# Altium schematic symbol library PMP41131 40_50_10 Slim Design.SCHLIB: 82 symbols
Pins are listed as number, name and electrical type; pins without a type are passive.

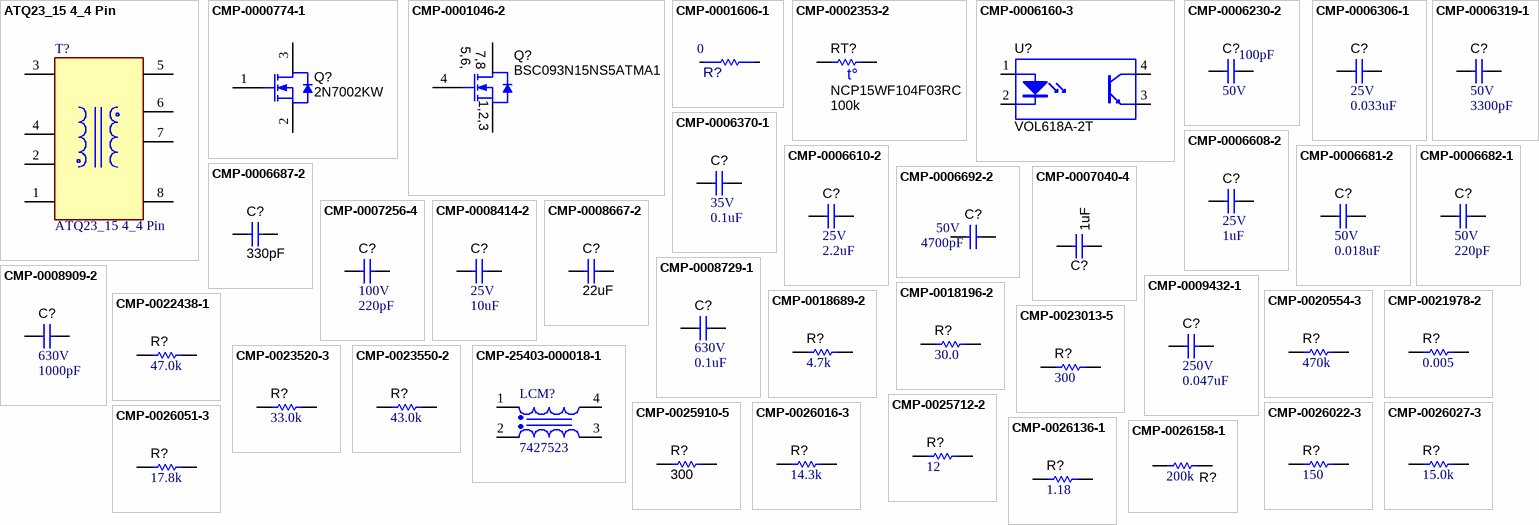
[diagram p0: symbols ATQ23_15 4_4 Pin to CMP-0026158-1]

## ATQ23_15 4_4 Pin
designator T?
footprint ATQ23.7_15 4+4 Pin
pins: 1, 2, 3, 4, 5, 6, 7, 8

## CMP-0000774-1
designator Q?, comment 2N7002KW
MOSFET, N-CH, 60 V, 0.31 A, SOT-323; Alternate Manufacturer: None; Manufacturer: Fairchild Semiconductor; SizeZ_mm: 1.1; ChType: N; Value1: 1; VdsMax_V: 60V; SizeX_mm: 2.2; Vgs_V: 2.1V; Value: 60V; Rdson45_ohm: 1.6; SizeArea_mm2: 4.84; AEC Category: Q101; IdsMax_A: 310mA; SizeAreaWB_mm2: 10.24; U/M: EA
footprint SOT-323 (Diodes Inc recommended land pattern.  2016-02-24)
pins: 1 G, 2 S, 3 D

## CMP-0001046-2
designator Q?, comment BSC093N15NS5ATMA1
MOSFET, N-CH, 150 V, 87 A, PG-TDSON-8; Alternate Manufacturer: None; Manufacturer: Infineon Technologies; SizeZ_mm: 1.12; ChType: N; Value2: 33 nC; VdsMax_V: 150V; SizeX_mm: 5.99; SizeY_mm: 4.9; Vgs_V: 20V; QgTyp_nC: 33; Value: 150V; SizeArea_mm2: 29.351; AEC Category: Q101; IdsMax_A: 87A; SizeAreaWB_mm2: 55.131; U/M: EA
footprint PG-TDSON-8 (Infineon recommended land pattern)
pins: 1 S, 2 S, 3 S, 4 G, 5 D, 6 D, 7 D, 8 D, 9 D

## CMP-0001606-1
designator R?, comment Res_ohm: 0  (hidden comment: CRCW04020000Z0EDHP)
RES Thick Film, 0Ω, 0.2W, 0402; Manufacturer: Vishay Dale; AEC Grade: Grade 0; AEC Qualified: Yes; Power_W: 200mW; SizeZ_mm: 0.4mm; VDC_V: 50V; Value: 0
footprint FP-CRCW04020000Z0EDHP_0402-MFG
footprint FP-CRCW04020000Z0EDHP_0402-IPC_C
footprint FP-CRCW04020000Z0EDHP_0402-IPC_B
footprint FP-CRCW04020000Z0EDHP_0402-IPC_A
pins: 1, 2

## CMP-0002353-2
designator RT?, comment NCP15WF104F03RC  value 100k
Thermistor NTC, 100k ohm, 1%, 0402; Manufacturer: MuRata; TaMax_C: 125°C; SizeX_mm: 1; SizeY_mm: 0.5; TaMin_C: -40°C; Power_W: 100mW; SizeZ_mm: 0.6; SizeAreaWB_mm2: 3; U/M: EA
footprint 0402S (Based on C0402S footprint from PADS legacy)
footprint 0402 (0402 from SM-752 data)
footprint 0402L (0402 from SM-752 data)
footprint 0402M (0402 from SM-752 data)
pins: 1, 2

## CMP-0006160-3
designator U?, comment VOL618A-2T
Optocoupler, 5 kV, 63-125% CTR, SMT; Manufacturer: Vishay-Semiconductor; Manufacturer: Vishay / Semiconductors; CTR (Max): 125%; SizeAreaWB_mm2: 74.42; CTR (Min): 63%; SizeZ_mm: 2.3; SizeX_mm: 10.2; SizeY_mm: 4.1; SizeArea_mm2: 41.82; Voltage_Isolation_Vrms: 5kV
footprint SOP254P1020X230-4 (VISHAY)
pins: 1 A, 2 K, 3 E, 4 C
1 alternate drawing of the same symbol

## CMP-0006230-2
designator C?, comment VDC_V: 50V  ValueDisplayed: 100pF  (hidden comment: 885012205055)
CAP, CERM, 100 pF, 50 V, +/- 10%, X7R, 0402; Manufacturer: Wurth Elektronik; TaMin_C: -55°C; Polarized: N; SizeAreaWB_mm2: 3; Value1: Unknown; U/M: EA; Value: 100pF; TaMax_C: 125°C; SizeZ_mm: 0.6; SizeX_mm: 1; SizeY_mm: 0.5; Cap_Case: 0402; CompType: Capacitor; AEC Category: Q200
footprint 0402 (0402 from SM-752 data)
footprint 0402S (Based on C0402S footprint from PADS legacy)
footprint 0402L (0402 from SM-752 data)
footprint 0402M (0402 from SM-752 data)
pins: 1, 2

## CMP-0006306-1
designator C?, comment VDC_V: 25V  ValueDisplayed: 0.033uF  (hidden comment: CGA2B1X7R1E333K050BC)
CAP, CERM, 0.033 uF, 25 V, +/- 10%, X7R, AEC-Q200 Grade 1, 0402; Manufacturer: TDK; TaMin_C: -55°C; Polarized: N; SizeAreaWB_mm2: 3; Value1: Unknown; U/M: EA; TaMax_C: 125°C; SizeZ_mm: 0.6; SizeX_mm: 1; SizeY_mm: 0.5; Cap_Case: 0402; CompType: Capacitor; AEC Qualified: Y; Cap_F: 33nF; AEC Category: Q200
footprint 0402 (0402 from SM-752 data)
footprint 0402S (Based on C0402S footprint from PADS legacy)
footprint 0402L (0402 from SM-752 data)
footprint 0402M (0402 from SM-752 data)
pins: 1, 2

## CMP-0006319-1
designator C?, comment VDC_V: 50V  ValueDisplayed: 3300pF  (hidden comment: CGA2B2X7R1H332K050BA)
CAP, CERM, 3300 pF, 50 V, +/- 10%, X7R, AEC-Q200 Grade 1, 0402; Manufacturer: TDK; TaMin_C: -55°C; ESR_ohm: 0.7852; Polarized: N; SizeAreaWB_mm2: 3; Value1: 0.785178 ohm; U/M: EA; Value: 3300pF; TaMax_C: 125°C; SizeZ_mm: 0.6; SizeX_mm: 1; SizeY_mm: 0.5; Cap_Case: 0402; CompType: Capacitor; AEC Qualified: Y; Cap_F: 3.3nF; IRMS_A: 272.902mA; AEC Category: Q200
footprint 0402 (0402 from SM-752 data)
footprint 0402S (Based on C0402S footprint from PADS legacy)
footprint 0402L (0402 from SM-752 data)
footprint 0402M (0402 from SM-752 data)
pins: 1, 2

## CMP-0006370-1
designator C?, comment VDC_V: 35V  ValueDisplayed: 0.1uF  (hidden comment: GMK105BJ104KV-F)
CAP, CERM, 0.1 uF, 35 V, +/- 10%, X5R, 0402; Manufacturer: Taiyo Yuden; TaMin_C: -55°C; Polarized: N; SizeAreaWB_mm2: 3; Value1: Unknown; U/M: EA; Value: 0.1uF; TaMax_C: 85°C; SizeZ_mm: 0.6; SizeX_mm: 1; SizeY_mm: 0.5; Cap_Case: 0402; CompType: Capacitor; Cap_F: 100nF; AEC Category: Q200
footprint 0402 (0402 from SM-752 data)
footprint 0402S (Based on C0402S footprint from PADS legacy)
footprint 0402L (0402 from SM-752 data)
footprint 0402M (0402 from SM-752 data)
pins: 1, 2

## CMP-0006608-2
designator C?, comment VDC_V: 25V  ValueDisplayed: 1uF  (hidden comment: GRM155R61E105KA12D)
CAP, CERM, 1 uF, 25 V, +/- 10%, X5R, 0402; Manufacturer: MuRata; TaMin_C: -55°C; Polarized: N; SizeAreaWB_mm2: 3; Value1: Unknown; U/M: EA; Value: 1uF; TaMax_C: 85°C; SizeZ_mm: 0.6; SizeX_mm: 1; SizeY_mm: 0.5; Cap_Case: 0402; CompType: Capacitor; Cap_F: 1µF; AEC Category: Q200
footprint 0402 (0402 from SM-752 data)
footprint 0402S (Based on C0402S footprint from PADS legacy)
footprint 0402L (0402 from SM-752 data)
footprint 0402M (0402 from SM-752 data)
pins: 1, 2

## CMP-0006610-2
designator C?, comment VDC_V: 25V  ValueDisplayed: 2.2uF  (hidden comment: GRM155R61E225KE11D)
CAP, CERM, 2.2 uF, 25 V, +/- 10%, X5R, 0402; Manufacturer: MuRata; TaMin_C: -55°C; Polarized: N; SizeAreaWB_mm2: 3; Value1: Unknown; U/M: EA; Value: 2.2uF; TaMax_C: 85°C; SizeZ_mm: 0.7; SizeX_mm: 1; SizeY_mm: 0.5; Cap_Case: 0402; CompType: Capacitor; Cap_F: 2.2µF; AEC Category: Q200
footprint 0402_070 (SMD, 2-Leads, Body 1.2x0.7mm, Height 0.7mm)
pins: 1, 2

## CMP-0006681-2
designator C?, comment VDC_V: 50V  ValueDisplayed: 0.018uF  (hidden comment: GRM155R71H183KA12D)
CAP, CERM, 0.018 uF, 50 V, +/- 10%, X7R, 0402; Manufacturer: MuRata; TaMin_C: -55°C; Polarized: N; SizeAreaWB_mm2: 3; Value1: Unknown; U/M: EA; TaMax_C: 125°C; SizeZ_mm: 0.6; SizeX_mm: 1; SizeY_mm: 0.5; Cap_Case: 0402; CompType: Capacitor; Cap_F: 18nF; AEC Category: Q200
footprint 0402 (0402 from SM-752 data)
footprint 0402S (Based on C0402S footprint from PADS legacy)
footprint 0402L (0402 from SM-752 data)
footprint 0402M (0402 from SM-752 data)
pins: 1, 2

## CMP-0006682-1
designator C?, comment VDC_V: 50V  ValueDisplayed: 220pF  (hidden comment: GRM155R71H221KA01D)
CAP, CERM, 220 pF, 50 V, +/- 10%, X7R, 0402; Manufacturer: MuRata; TaMin_C: -55°C; Polarized: N; SizeAreaWB_mm2: 3; Value1: Unknown; U/M: EA; Value: 220pF; TaMax_C: 125°C; SizeZ_mm: 0.6; SizeX_mm: 1; SizeY_mm: 0.5; Cap_Case: 0402; CompType: Capacitor; AEC Category: Q200
footprint 0402 (0402 from SM-752 data)
footprint 0402S (Based on C0402S footprint from PADS legacy)
footprint 0402L (0402 from SM-752 data)
footprint 0402M (0402 from SM-752 data)
pins: 1, 2

## CMP-0006687-2
designator C?, comment ValueDisplayed: 330pF  (hidden comment: GRM155R71H331KA01D)
CAP, CERM, 330 pF, 50 V, +/- 10%, X7R, 0402; Manufacturer: MuRata; TaMin_C: -55°C; Polarized: N; SizeAreaWB_mm2: 3; Value1: Unknown; U/M: EA; Value: 330pF; TaMax_C: 125°C; SizeZ_mm: 0.6; SizeX_mm: 1; SizeY_mm: 0.5; Cap_Case: 0402; Value2: 50V; CompType: Capacitor; AEC Category: Q200
footprint 0402 (0402 from SM-752 data)
footprint 0402S (Based on C0402S footprint from PADS legacy)
footprint 0402L (0402 from SM-752 data)
footprint 0402M (0402 from SM-752 data)
pins: 1, 2

## CMP-0006692-2
designator C?, comment VDC_V: 50V  ValueDisplayed: 4700pF  (hidden comment: GRM155R71H472KA01D)
CAP, CERM, 4700 pF, 50 V, +/- 10%, X7R, 0402; Manufacturer: MuRata; TaMin_C: -55°C; Polarized: N; SizeAreaWB_mm2: 3; Value1: Unknown; U/M: EA; Value: 4700pF; TaMax_C: 125°C; SizeZ_mm: 0.6; SizeX_mm: 1; SizeY_mm: 0.5; Cap_Case: 0402; CompType: Capacitor; Cap_F: 4.7nF; AEC Category: Q200
footprint 0402 (0402 from SM-752 data)
footprint 0402S (Based on C0402S footprint from PADS legacy)
footprint 0402L (0402 from SM-752 data)
footprint 0402M (0402 from SM-752 data)
pins: 1, 2

## CMP-0007040-4
designator C?, comment ValueDisplayed: 1uF  (hidden comment: C1608X7R1E105K080AB)
CAP, CERM, 1 µF, 25 V, +/- 10%, X7R, 0603; Manufacturer: TDK; Polarized: N; CompType: Capacitor; Value: 1uF; U/M: EA; Cap_F: 1µF; Value1: Unknown; VDC_V: 25V; TaMin_C: -55°C; TaMax_C: 125°C; Cap_Case: 0603; AEC Category: Q200; SizeArea_mm2: 1.28; SizeAreaWB_mm2: 4.68; SizeX_mm: 1.6; SizeY_mm: 0.8; SizeZ_mm: 1
footprint 0603 (0603 from SM-752 data)
footprint 0603_HV (Ernesto recommended land pattern.  26 mil between pads.)
footprint 0603L (0603 from SM-752 data)
footprint 0603S
footprint 0603M (0603 from SM-752 data)
pins: 1, 2

## CMP-0007256-4
designator C?, comment VDC_V: 100V  ValueDisplayed: 220pF  (hidden comment: GRM1885C2A221JA01D)
CAP, CERM, 220 pF, 100 V, +/- 5%, C0G/NP0, 0603; Manufacturer: MuRata; TaMin_C: -55°C; Polarized: N; SizeAreaWB_mm2: 4.68; Value1: Unknown; U/M: EA; Value: 220pF; TaMax_C: 125°C; SizeZ_mm: 1; SizeX_mm: 1.6; SizeY_mm: 0.8; Cap_Case: 0603; SizeArea_mm2: 1.28; CompType: Capacitor; AEC Category: Q200
footprint 0603 (0603 from SM-752 data)
footprint 0603_HV (Ernesto recommended land pattern.  26 mil between pads.)
footprint 0603L (0603 from SM-752 data)
footprint 0603S
footprint 0603M (0603 from SM-752 data)
pins: 1, 2

## CMP-0008414-2
designator C?, comment VDC_V: 25V  ValueDisplayed: 10uF  (hidden comment: TMK212BBJ106KG-T)
CAP, CERM, 10 uF, 25 V, +/- 10%, X5R, 0805; Manufacturer: Taiyo Yuden; TaMin_C: -55°C; Polarized: N; SizeAreaWB_mm2: 6.75; Value1: Unknown; U/M: EA; Value: 10uF; TaMax_C: 85°C; SizeZ_mm: 1.45; SizeX_mm: 2; SizeY_mm: 1.25; Cap_Case: 0805; SizeArea_mm2: 2.5; CompType: Capacitor; Cap_F: 10µF; AEC Category: Q200
footprint 0805_HV (0805 with 30mil clearance between pads)
footprint 0805M (0805 from SM-752 data)
footprint 0805 (0805 from SM-752 data)
footprint 0805L (0805 from SM-752 data)
footprint 0805_HV1 (Custom footprint based on analyzing multiple manufacturer recommendations)
pins: 1, 2

## CMP-0008667-2
designator C?, comment ValueDisplayed: 22uF  (hidden comment: C3216X5R1V226M160AC)
CAP, CERM, 22 uF, 35 V, +/- 20%, X5R, 1206; Manufacturer: TDK; TaMin_C: -55°C; ESR_ohm: 2.398m; Polarized: N; SizeAreaWB_mm2: 10.92; Value1: 0.002398 ohm; U/M: EA; Value: 22uF; TaMax_C: 85°C; SizeZ_mm: 1.8; SizeX_mm: 3.2; SizeY_mm: 1.6; Cap_Case: 1206_180; Value2: 35V; SizeArea_mm2: 5.12; CompType: Capacitor; Cap_F: 22µF; IRMS_A: 4.68507A; AEC Category: Q200
footprint 1206_180
footprint 1206_180L (1206_180)
footprint 1206_180M (1206_180)
pins: 1, 2

## CMP-0008729-1
designator C?, comment VDC_V: 630V  ValueDisplayed: 0.1uF  (hidden comment: C3216X7T2W104M160AA)
CAP, CERM, 0.1 uF, 450 V, +/- 20%, X7T, 1206; Manufacturer: TDK; TaMin_C: -55°C; Polarized: N; SizeAreaWB_mm2: 10.92; Value1: Unknown; U/M: EA; Value: 0.1uF; TaMax_C: 125°C; SizeZ_mm: 1.8; SizeX_mm: 3.2; SizeY_mm: 1.6; Cap_Case: 1206; Value2: 450V; SizeArea_mm2: 5.12; CompType: Capacitor; Cap_F: 100nF; AEC Category: Q200
footprint 1206_180
footprint 1206_180L (1206_180)
footprint 1206_180M (1206_180)
pins: 1, 2

## CMP-0008909-2
designator C?, comment VDC_V: 630V  ValueDisplayed: 1000pF  (hidden comment: GRM31BR72J102KW01L)
CAP, CERM, 1000 pF, 630 V, +/- 10%, X7R, 1206; Manufacturer: MuRata; TaMin_C: -55°C; Polarized: N; SizeAreaWB_mm2: 10.92; Value1: Unknown; U/M: EA; Value: 1000pF; TaMax_C: 125°C; SizeZ_mm: 1.35; SizeX_mm: 3.2; SizeY_mm: 1.6; Cap_Case: 1206; SizeArea_mm2: 5.12; CompType: Capacitor; Cap_F: 1nF; AEC Category: Q200
footprint 1206 (1206 from SM-752 data)
footprint 1206L (1206 from SM-752 data)
footprint 1206M (1206 from SM-752 data)
pins: 1, 2

## CMP-0009432-1
designator C?, comment VDC_V: 250V  ValueDisplayed: 0.047uF  (hidden comment: GA355ER7GB473KW01L)
CAP, CERM, 0.047 uF, 250 V, +/- 10%, X7R, 2220; Manufacturer: MuRata; TaMin_C: -55°C; Polarized: N; SizeAreaWB_mm2: 53.9; Value1: Unknown; U/M: EA; TaMax_C: 125°C; SizeZ_mm: 2.8; SizeX_mm: 5.7; SizeY_mm: 5; Cap_Case: 2220; SizeArea_mm2: 28.5; CompType: Capacitor; Cap_F: 47nF; AEC Category: Q200
footprint 2220_280 (Chip Capacitor, Body 5.7x5.0mm, IPC Medium Density)
footprint 2220_280L (Chip Capacitor, Body 5.7x5.0mm, IPC High Density)
footprint 2220_280M (Chip Capacitor, Body 5.7x5.0mm, IPC Low Density)
pins: 1, 2

## CMP-0018196-2
designator R?, comment ValueDisplayed: 30.0  (hidden comment: RC1206FR-0730RL)
RES, 30.0, 1%, 0.25 W, 1206; Manufacturer: Yageo America; Power_W: 250mW; TempCo: 100 ppm/C; Value_Code: 30R0; U/M: EA; Value: 30.0; Res_ohm: 30; SizeX_mm: 3.2; SizeY_mm: 1.6; SizeZ_mm: 1.35; Value2: 0.25W; SizeArea_mm2: 5.12; CompType: Resistor; VDC_V: 200V; AEC Category: Q200
footprint 1206 (1206 from SM-752 data)
footprint 1206L (1206 from SM-752 data)
footprint 1206M (1206 from SM-752 data)
pins: 1, 2

## CMP-0018689-2
designator R?, comment ValueDisplayed: 4.7k  (hidden comment: CRCW12064K70JNEA)
RES, 4.7 k, 5%, 0.25 W, 1206; Manufacturer: Vishay-Dale; Manufacturer: Vishay/Dale; Power_W: 250mW; TempCo: 200 ppm/C; Value_Code: 4k70; U/M: EA; Value: 4.7k; EIA_Code: E24; SizeX_mm: 3.2; SizeY_mm: 1.6; SizeZ_mm: 1.35; Value2: 0.25W; SizeArea_mm2: 5.12; CompType: Resistor; VDC_V: 200V; AEC Category: Q200
footprint 1206 (1206 from SM-752 data)
footprint 1206L (1206 from SM-752 data)
footprint 1206M (1206 from SM-752 data)
pins: 1, 2

## CMP-0020554-3
designator R?, comment ValueDisplayed: 470k  (hidden comment: CRCW0805470KJNEA)
RES, 470 k, 5%, 0.125 W, AEC-Q200 Grade 0, 0805; Manufacturer: Vishay-Dale; Manufacturer: Vishay/Dale; Power_W: 125mW; TempCo: 200 ppm/C; Value: 470k; EIA_Code: E24; SizeX_mm: 2; SizeY_mm: 1.25; SizeZ_mm: 1.45; Value2: 0.125W; SizeArea_mm2: 2.5; CompType: Resistor; AEC Qualified: Y; VDC_V: 150V; AEC Category: Q200; AEC Grade: 0
footprint 0805_HV (0805 with 30mil clearance between pads)
footprint 0805M (0805 from SM-752 data)
footprint 0805 (0805 from SM-752 data)
footprint 0805L (0805 from SM-752 data)
footprint 0805_HV1 (Custom footprint based on analyzing multiple manufacturer recommendations)
pins: 1, 2

## CMP-0021978-2
designator R?, comment ValueDisplayed: 0.005  (hidden comment: WSL08055L000FEA)
RES, 0.005, 1%, 0.25 W, 0805; Manufacturer: Vishay-Dale; Manufacturer: Vishay; Power_W: 250mW; TempCo: 110 ppm/C; Value_Code: 5L000; U/M: EA; Value: 0.005; EIA_Code: E96; Res_ohm: 5m; SizeX_mm: 2.03; SizeY_mm: 1.27; SizeZ_mm: 0.584; Value2: 0.25W; SizeArea_mm2: 2.5781; CompType: Resistor; AEC Qualified: N; AEC Category: Q200
footprint WSL0805 (Vishay)
pins: 1, 2

## CMP-0022438-1
designator R?, comment ValueDisplayed: 47.0k  (hidden comment: CRCW060347K0FKEA)
RES, 47.0 k, 1%, 0.1 W, AEC-Q200 Grade 0, 0603; Manufacturer: Vishay-Dale; Manufacturer: Vishay/Dale; Power_W: 100mW; TempCo: 100 ppm/C; Value_Code: 47k0; U/M: EA; Value: 47.0k; Res_ohm: 47k; SizeX_mm: 1.6; SizeY_mm: 0.8; SizeZ_mm: 1; Value2: 0.1W; SizeArea_mm2: 1.28; CompType: Resistor; AEC Qualified: Y; VDC_V: 75V; AEC Grade: 0; AEC Category: Q200
footprint 0603 (0603 from SM-752 data)
footprint 0603_HV (Ernesto recommended land pattern.  26 mil between pads.)
footprint 0603L (0603 from SM-752 data)
footprint 0603S
footprint 0603M (0603 from SM-752 data)
pins: 1, 2

## CMP-0023013-5
designator R?, comment ValueDisplayed: 300  (hidden comment: RC0603FR-07300RL)
RES, 300, 1%, 0.1 W, 0603; Manufacturer: Yageo; Power_W: 100mW; TempCo: 100 ppm/C; Value_Code: 300R; Value: 300; SizeX_mm: 1.6; SizeY_mm: 0.8; SizeZ_mm: 1; Value2: 0.1W; SizeArea_mm2: 1.28; CompType: Resistor; AEC Qualified: N; VDC_V: 75V; AEC Category: Q200; SizeAreaWB_mm2: 4.68
footprint 0603 (0603 from SM-752 data)
footprint 0603_HV (Ernesto recommended land pattern.  26 mil between pads.)
footprint 0603L (0603 from SM-752 data)
footprint 0603S
footprint 0603M (0603 from SM-752 data)
pins: 1, 2

## CMP-0023520-3
designator R?, comment ValueDisplayed: 33.0k  (hidden comment: RG1608P-333-B-T5)
RES, 33.0 k, 0.1%, 0.1 W, 0603; Manufacturer: Susumu Co Ltd; Power_W: 100mW; TempCo: 25 ppm/C; Value_Code: 33k0; U/M: EA; Value: 33.0k; Res_ohm: 33k; SizeX_mm: 1.6; SizeY_mm: 0.8; SizeZ_mm: 1; Value2: 0.1W; SizeArea_mm2: 1.28; CompType: Resistor; VDC_V: 75V; AEC Category: Q200
footprint 0603 (0603 from SM-752 data)
footprint 0603_HV (Ernesto recommended land pattern.  26 mil between pads.)
footprint 0603L (0603 from SM-752 data)
footprint 0603S
footprint 0603M (0603 from SM-752 data)
pins: 1, 2

## CMP-0023550-2
designator R?, comment ValueDisplayed: 43.0k  (hidden comment: RG1608P-433-B-T5)
RES, 43.0 k, 0.1%, 0.1 W, 0603; Manufacturer: Susumu Co Ltd; Power_W: 100mW; TempCo: 25 ppm/C; Value_Code: 43k0; U/M: EA; Value: 43.0k; Res_ohm: 43k; SizeX_mm: 1.6; SizeY_mm: 0.8; SizeZ_mm: 1; Value2: 0.1W; SizeArea_mm2: 1.28; CompType: Resistor; VDC_V: 75V; AEC Category: Q200
footprint 0603 (0603 from SM-752 data)
footprint 0603_HV (Ernesto recommended land pattern.  26 mil between pads.)
footprint 0603L (0603 from SM-752 data)
footprint 0603S
footprint 0603M (0603 from SM-752 data)
pins: 1, 2

## CMP-25403-000018-1
designator LCM?, comment 7427523
WE-CMS SMT Bead Array, size 9085, 83Ohm, 21A; Manufacturer: Wurth Elektronik; Manufacturer: Wurth Electronics; Case/Size Code: 9085; DC Resistance: 3mOhm; Impedance @25MHz: 54Ohm; Rated Voltage: 80V
footprint WE-CMS_9085 (Common Mode SMT Bead, body 9.00x8.50mm)
pins: 1, 2, 3, 4

## CMP-0025712-2
designator R?, comment ValueDisplayed: 12  (hidden comment: CRCW060312R0JNEA)
RES, 12, 5%, 0.1 W, 0603; Manufacturer: Vishay-Dale; Power_W: 100mW; TempCo: 200 ppm/C; Value_Code: 12R0; U/M: EA; Value: 12; EIA_Code: E24; SizeX_mm: 1.6; SizeY_mm: 0.8; SizeZ_mm: 1; Value2: 0.1W; SizeArea_mm2: 1.28; CompType: Resistor; VDC_V: 75V; AEC Category: Q200
footprint 0603 (0603 from SM-752 data)
footprint 0603_HV (Ernesto recommended land pattern.  26 mil between pads.)
footprint 0603L (0603 from SM-752 data)
footprint 0603S
footprint 0603M (0603 from SM-752 data)
pins: 1, 2

## CMP-0025910-5
designator R?, comment ValueDisplayed: 300  (hidden comment: RC0603JR-07300RL)
RES, 300, 5%, 0.1 W, 0603; Manufacturer: Yageo; Power_W: 100mW; TempCo: 100 ppm/C; Value_Code: 300R; Value: 300; EIA_Code: E24; SizeX_mm: 1.6; SizeY_mm: 0.8; SizeZ_mm: 1; Value2: 0.1W; SizeArea_mm2: 1.28; CompType: Resistor; AEC Qualified: N; VDC_V: 75V; AEC Category: Q200; SizeAreaWB_mm2: 4.68
footprint 0603 (0603 from SM-752 data)
footprint 0603_HV (Ernesto recommended land pattern.  26 mil between pads.)
footprint 0603L (0603 from SM-752 data)
footprint 0603S
footprint 0603M (0603 from SM-752 data)
pins: 1, 2

## CMP-0026016-3
designator R?, comment ValueDisplayed: 14.3k  (hidden comment: CRCW040214K3FKED)
RES, 14.3 k, 1%, 0.063 W, AEC-Q200 Grade 0, 0402; Manufacturer: Vishay-Dale; Manufacturer: Vishay / Dale; Power_W: 63mW; TempCo: 100 ppm/C; Value_Code: 14k3; Value: 14.3k; EIA_Code: E96; SizeX_mm: 1; SizeY_mm: 0.5; SizeZ_mm: 0.6; Value2: 0.063W; CompType: Resistor; AEC Qualified: Y; VDC_V: 50V; AEC Category: Q200; AEC Grade: 0
footprint 0402 (0402 from SM-752 data)
footprint 0402S (Based on C0402S footprint from PADS legacy)
footprint 0402L (0402 from SM-752 data)
footprint 0402M (0402 from SM-752 data)
pins: 1, 2

## CMP-0026022-3
designator R?, comment ValueDisplayed: 150  (hidden comment: CRCW0402150RFKED)
RES, 150, 1%, 0.063 W, AEC-Q200 Grade 0, 0402; Manufacturer: Vishay-Dale; Manufacturer: Vishay / Dale; Power_W: 63mW; TempCo: 100 ppm/C; Value_Code: 150R; Value: 150; EIA_Code: E96; SizeX_mm: 1; SizeY_mm: 0.5; SizeZ_mm: 0.6; Value2: 0.063W; CompType: Resistor; AEC Qualified: Y; VDC_V: 50V; AEC Category: Q200; AEC Grade: 0
footprint 0402 (0402 from SM-752 data)
footprint 0402S (Based on C0402S footprint from PADS legacy)
footprint 0402L (0402 from SM-752 data)
footprint 0402M (0402 from SM-752 data)
pins: 1, 2

## CMP-0026027-3
designator R?, comment ValueDisplayed: 15.0k  (hidden comment: CRCW040215K0FKED)
RES, 15.0 k, 1%, 0.063 W, AEC-Q200 Grade 0, 0402; Manufacturer: Vishay-Dale; Manufacturer: Vishay / Dale; Power_W: 63mW; TempCo: 100 ppm/C; Value_Code: 15k0; Value: 15.0k; EIA_Code: E96; Res_ohm: 15k; SizeX_mm: 1; SizeY_mm: 0.5; SizeZ_mm: 0.6; Value2: 0.063W; CompType: Resistor; AEC Qualified: Y; VDC_V: 50V; AEC Category: Q200; AEC Grade: 0
footprint 0402 (0402 from SM-752 data)
footprint 0402S (Based on C0402S footprint from PADS legacy)
footprint 0402L (0402 from SM-752 data)
footprint 0402M (0402 from SM-752 data)
pins: 1, 2

## CMP-0026051-3
designator R?, comment ValueDisplayed: 17.8k  (hidden comment: CRCW040217K8FKED)
RES, 17.8 k, 1%, 0.063 W, AEC-Q200 Grade 0, 0402; Manufacturer: Vishay-Dale; Manufacturer: Vishay / Dale; Power_W: 63mW; TempCo: 100 ppm/C; Value_Code: 17k8; Value: 17.8k; EIA_Code: E96; SizeX_mm: 1; SizeY_mm: 0.5; SizeZ_mm: 0.6; Value2: 0.063W; CompType: Resistor; AEC Qualified: Y; VDC_V: 50V; AEC Category: Q200; AEC Grade: 0
footprint 0402 (0402 from SM-752 data)
footprint 0402S (Based on C0402S footprint from PADS legacy)
footprint 0402L (0402 from SM-752 data)
footprint 0402M (0402 from SM-752 data)
pins: 1, 2

## CMP-0026136-1
designator R?, comment ValueDisplayed: 1.18  (hidden comment: CRCW04021R18FKED)
RES, 1.18, 1%, 0.063 W, 0402; Manufacturer: Vishay-Dale; Power_W: 63mW; TempCo: 100 ppm/C; Value_Code: 1R18; U/M: EA; Value: 1.18; EIA_Code: E96; SizeX_mm: 1; SizeY_mm: 0.5; SizeZ_mm: 0.6; Value2: 0.063W; CompType: Resistor; VDC_V: 50V; AEC Category: Q200
footprint 0402 (0402 from SM-752 data)
footprint 0402S (Based on C0402S footprint from PADS legacy)
footprint 0402L (0402 from SM-752 data)
footprint 0402M (0402 from SM-752 data)
pins: 1, 2

## CMP-0026158-1
designator R?, comment ValueDisplayed: 200k  (hidden comment: CRCW0402200KFKED)
RES, 200 k, 1%, 0.063 W, 0402; Manufacturer: Vishay-Dale; Power_W: 63mW; TempCo: 100 ppm/C; U/M: EA; Value: 200k; EIA_Code: E96; SizeX_mm: 1; SizeY_mm: 0.5; SizeZ_mm: 0.6; Value2: 0.063W; CompType: Resistor; VDC_V: 50V; AEC Category: Q200
footprint 0402 (0402 from SM-752 data)
footprint 0402S (Based on C0402S footprint from PADS legacy)
footprint 0402L (0402 from SM-752 data)
footprint 0402M (0402 from SM-752 data)
pins: 1, 2

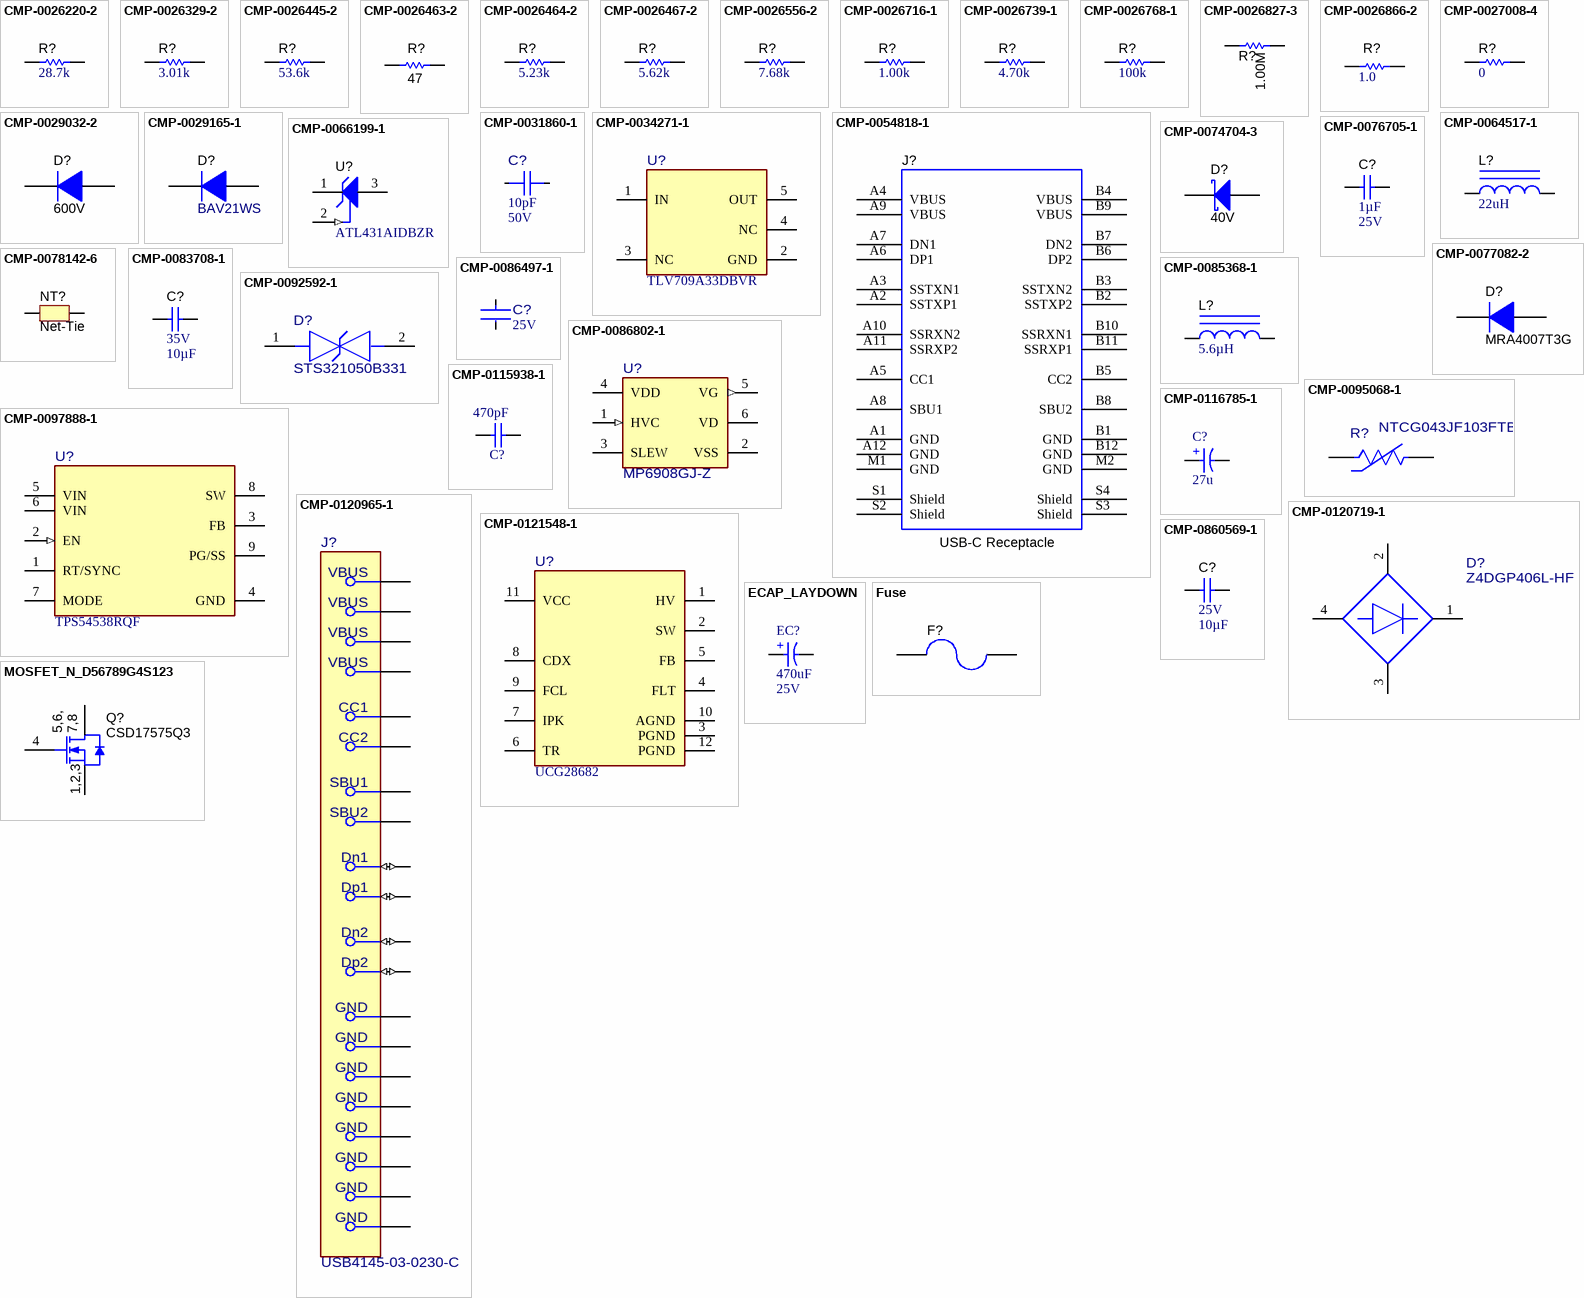
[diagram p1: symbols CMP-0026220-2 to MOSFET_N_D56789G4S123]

## CMP-0026220-2
designator R?, comment ValueDisplayed: 28.7k  (hidden comment: CRCW040228K7FKED)
RES, 28.7 k, 1%, 0.063 W, AEC-Q200 Grade 0, 0402; Manufacturer: Vishay-Dale; Power_W: 63mW; TempCo: 100 ppm/C; Value_Code: 28k7; Value: 28.7k; EIA_Code: E96; SizeX_mm: 1; SizeY_mm: 0.5; SizeZ_mm: 0.6; Value2: 0.063W; CompType: Resistor; AEC Qualified: Y; VDC_V: 50V; AEC Category: Q200; AEC Grade: 0
footprint 0402 (0402 from SM-752 data)
footprint 0402S (Based on C0402S footprint from PADS legacy)
footprint 0402L (0402 from SM-752 data)
footprint 0402M (0402 from SM-752 data)
pins: 1, 2

## CMP-0026329-2
designator R?, comment ValueDisplayed: 3.01k  (hidden comment: CRCW04023K01FKED)
RES, 3.01 k, 1%, 0.063 W, AEC-Q200 Grade 0, 0402; Manufacturer: Vishay-Dale; Power_W: 63mW; TempCo: 100 ppm/C; Value_Code: 3k01; Value: 3.01k; EIA_Code: E96; SizeX_mm: 1; SizeY_mm: 0.5; SizeZ_mm: 0.6; Value2: 0.063W; CompType: Resistor; AEC Qualified: Y; VDC_V: 50V; AEC Category: Q200; AEC Grade: 0
footprint 0402 (0402 from SM-752 data)
footprint 0402S (Based on C0402S footprint from PADS legacy)
footprint 0402L (0402 from SM-752 data)
footprint 0402M (0402 from SM-752 data)
pins: 1, 2

## CMP-0026445-2
designator R?, comment ValueDisplayed: 53.6k  (hidden comment: CRCW040253K6FKED)
RES, 53.6 k, 1%, 0.063 W, AEC-Q200 Grade 0, 0402; Manufacturer: Vishay-Dale; Power_W: 63mW; TempCo: 100 ppm/C; Value_Code: 53k6; Value: 53.6k; EIA_Code: E96; SizeX_mm: 1; SizeY_mm: 0.5; SizeZ_mm: 0.6; Value2: 0.063W; CompType: Resistor; AEC Qualified: Y; VDC_V: 50V; AEC Category: Q200; AEC Grade: 0
footprint 0402 (0402 from SM-752 data)
footprint 0402S (Based on C0402S footprint from PADS legacy)
footprint 0402L (0402 from SM-752 data)
footprint 0402M (0402 from SM-752 data)
pins: 1, 2

## CMP-0026463-2
designator R?, comment ValueDisplayed: 47  (hidden comment: CRCW040247R0JNED)
RES, 47, 5%, 0.063 W, 0402; Manufacturer: Vishay-Dale; Power_W: 63mW; TempCo: 200 ppm/C; Value: 47; EIA_Code: E96; SizeX_mm: 1; SizeY_mm: 0.5; SizeZ_mm: 0.6; Value2: 0.063W; CompType: Resistor; AEC Qualified: Y; VDC_V: 50V; AEC Category: Q200; AEC Grade: 0
footprint 0402 (0402 from SM-752 data)
footprint 0402S (Based on C0402S footprint from PADS legacy)
footprint 0402L (0402 from SM-752 data)
footprint 0402M (0402 from SM-752 data)
pins: 1, 2

## CMP-0026464-2
designator R?, comment ValueDisplayed: 5.23k  (hidden comment: CRCW04025K23FKED)
RES, 5.23 k, 1%, 0.063 W, AEC-Q200 Grade 0, 0402; Manufacturer: Vishay-Dale; Power_W: 63mW; TempCo: 100 ppm/C; Value_Code: 5k23; Value: 5.23k; EIA_Code: E96; SizeX_mm: 1; SizeY_mm: 0.5; SizeZ_mm: 0.6; Value2: 0.063W; CompType: Resistor; AEC Qualified: Y; VDC_V: 50V; AEC Category: Q200; AEC Grade: 0
footprint 0402 (0402 from SM-752 data)
footprint 0402S (Based on C0402S footprint from PADS legacy)
footprint 0402L (0402 from SM-752 data)
footprint 0402M (0402 from SM-752 data)
pins: 1, 2

## CMP-0026467-2
designator R?, comment ValueDisplayed: 5.62k  (hidden comment: CRCW04025K62FKED)
RES, 5.62 k, 1%, 0.063 W, AEC-Q200 Grade 0, 0402; Manufacturer: Vishay-Dale; Power_W: 63mW; TempCo: 100 ppm/C; Value_Code: 5k62; Value: 5.62k; EIA_Code: E96; SizeX_mm: 1; SizeY_mm: 0.5; SizeZ_mm: 0.6; Value2: 0.063W; CompType: Resistor; AEC Qualified: Y; VDC_V: 50V; AEC Category: Q200; AEC Grade: 0
footprint 0402 (0402 from SM-752 data)
footprint 0402S (Based on C0402S footprint from PADS legacy)
footprint 0402L (0402 from SM-752 data)
footprint 0402M (0402 from SM-752 data)
pins: 1, 2

## CMP-0026556-2
designator R?, comment ValueDisplayed: 7.68k  (hidden comment: CRCW04027K68FKED)
RES, 7.68 k, 1%, 0.063 W, AEC-Q200 Grade 0, 0402; Manufacturer: Vishay-Dale; Power_W: 63mW; TempCo: 100 ppm/C; Value_Code: 7k68; Value: 7.68k; EIA_Code: E96; SizeX_mm: 1; SizeY_mm: 0.5; SizeZ_mm: 0.6; Value2: 0.063W; CompType: Resistor; AEC Qualified: Y; VDC_V: 50V; AEC Category: Q200; AEC Grade: 0
footprint 0402 (0402 from SM-752 data)
footprint 0402S (Based on C0402S footprint from PADS legacy)
footprint 0402L (0402 from SM-752 data)
footprint 0402M (0402 from SM-752 data)
pins: 1, 2

## CMP-0026716-1
designator R?, comment ValueDisplayed: 1.00k  (hidden comment: MCR01MZPF1001)
RES, 1.00 k, 1%, 0.063 W, 0402; Manufacturer: Rohm; Power_W: 63mW; TempCo: 100 ppm/C; Value_Code: 1k00; U/M: EA; Value: 1.00k; EIA_Code: E96; Res_ohm: 1k; SizeX_mm: 1; SizeY_mm: 0.5; SizeZ_mm: 0.6; Value2: 0.063W; CompType: Resistor; AEC Qualified: N; VDC_V: 50V; AEC Category: Q200
footprint 0402 (0402 from SM-752 data)
footprint 0402S (Based on C0402S footprint from PADS legacy)
footprint 0402L (0402 from SM-752 data)
footprint 0402M (0402 from SM-752 data)
pins: 1, 2

## CMP-0026739-1
designator R?, comment ValueDisplayed: 4.70k  (hidden comment: RC0402FR-074K7L)
RES, 4.70 k, 1%, 0.0625 W, 0402; Manufacturer: Yageo America; Power_W: 62.5mW; TempCo: 100 ppm/C; Value_Code: 4k70; U/M: EA; Value: 4.70k; Res_ohm: 4.7k; SizeX_mm: 1; SizeY_mm: 0.5; SizeZ_mm: 0.6; CompType: Resistor; AEC Qualified: N; VDC_V: 50V; AEC Category: Q200
footprint 0402 (0402 from SM-752 data)
footprint 0402S (Based on C0402S footprint from PADS legacy)
footprint 0402L (0402 from SM-752 data)
footprint 0402M (0402 from SM-752 data)
pins: 1, 2

## CMP-0026768-1
designator R?, comment ValueDisplayed: 100k  (hidden comment: CRCW0402100KDHEDP)
RES, 100 k, 0.5%, 0.063 W, 0402; Manufacturer: Vishay-Dale; Power_W: 63mW; TempCo: 50 ppm/C; U/M: EA; Value: 100k; EIA_Code: E192; SizeX_mm: 1; SizeY_mm: 0.5; SizeZ_mm: 0.6; Value2: 0.063W; CompType: Resistor; VDC_V: 50V; AEC Category: Q200
footprint 0402 (0402 from SM-752 data)
footprint 0402S (Based on C0402S footprint from PADS legacy)
footprint 0402L (0402 from SM-752 data)
footprint 0402M (0402 from SM-752 data)
pins: 1, 2

## CMP-0026827-3
designator R?, comment ValueDisplayed: 1.00M  (hidden comment: RMCF0402FT1M00)
RES, 1.00 M, 1%, 0.063 W, AEC-Q200 Grade 0, 0402; Manufacturer: Stackpole Electronics Inc; Manufacturer: Vishay / Dale; Manufacturer Part Number: CRCW040210R0JNED; CompType: Resistor; Value: 1.0Meg; Power_W: 63mW; Value2: 0.063W; VDC_V: 50V; TempCo: 200 ppm/C; SizeArea_mm2: 0.5; SizeX_mm: 1; SizeZ_mm: 0.6; EIA_Code: E24; AEC Category: Q200; AEC Qualified: Y; AEC Grade: 0
footprint 0402 (0402 from SM-752 data)
footprint 0402S (Based on C0402S footprint from PADS legacy)
footprint 0402L (0402 from SM-752 data)
footprint 0402M (0402 from SM-752 data)
pins: 1, 2

## CMP-0026866-2
designator R?, comment ValueDisplayed: 1.0  (hidden comment: CRCW04021R00JNED)
RES, 1.0, 5%, 0.063 W, 0402; Manufacturer: Vishay-Dale; Manufacturer: Vishay / Dale; Power_W: 63mW; TempCo: 200 ppm/C; Value_Code: 1R00; U/M: EA; Value: 1.0; EIA_Code: E24; Res_ohm: 1; SizeY_mm: 0.5; SizeZ_mm: 0.6; Value2: 0.063W; CompType: Resistor; VDC_V: 50V; AEC Category: Q200
footprint 0402 (0402 from SM-752 data)
footprint 0402S (Based on C0402S footprint from PADS legacy)
footprint 0402L (0402 from SM-752 data)
footprint 0402M (0402 from SM-752 data)
pins: 1, 2

## CMP-0027008-4
designator R?, comment ValueDisplayed: 0  (hidden comment: CRCW02010000Z0ED)
RES, 0, 5%, 0.05 W, 0201; Manufacturer: Vishay-Dale; Manufacturer: Vishay / Dale; Power_W: 50mW; TempCo: ppm/C; Value_Code: 0000; Value: 0; EIA_Code: E24; SizeX_mm: 0.6; SizeY_mm: 0.3; SizeZ_mm: 0.26; Value2: 0.05W; SizeArea_mm2: 0.18; CompType: Resistor; AEC Qualified: N; AEC Category: Q200
footprint 0201 (Data from Kemet datasheet CC101_COM dated 7/28/11)
footprint 0201_Silk (Data from Kemet datasheet CC101_COM dated 7/28/11)
footprint 0201L (Data from Kemet datasheet CC101_COM dated 7/28/11)
footprint 0201M (Data from Kemet datasheet CC101_COM dated 7/28/11)
pins: 1, 2

## CMP-0029032-2
designator D?, comment value 600V  (hidden comment: ES1JFL)
Diode, Switching, 600 V, 1 A, SOD-123; Manufacturer: ON Semiconductor; Manufacturer Part Number: MMSD4148T1G; SizeY_mm: 1.7; Io_A: 1A; SizeAreaWB_mm2: 13.095; SizeArea_mm2: 6.545; Vf_V: 1V; TJmax_C: 150°C; SizeX_mm: 3.85; SizeZ_mm: 1.35; Green_Lifecycle: Active; Green_REACh: Passed
footprint SOD-123 (On Semi recommended land pattern)
pins: 1 K, 2 A

## CMP-0029165-1
designator D?, comment BAV21WS
Diode, Switching, 250 V, 0.25 A, AEC-Q101, SOD-323; Manufacturer: Diodes Inc.; Manufacturer: Diodes; Manufacturer Part Number: BAV21WS-7-F; Io_A: 250mA; Green_Lifecycle: Active; SizeAreaWB_mm2: 8.695; Vr_V: 250V; Green_REACh: Passed; Value1: 0.25A; TJmax_C: 150°C; U/M: EA; Value: 250V; SizeZ_mm: 1; SizeX_mm: 2.7; SizeY_mm: 1.35; Vf_V: 1.25V; SizeArea_mm2: 3.645; AEC Qualified: Y; AEC Category: Q101
footprint SOD-323 (NXP recommended land pattern)
pins: 1 K, 2 A

## CMP-0031860-1
designator C?, comment ValueDisplayed: 10pF  VDC_V: 50V  (hidden comment: CGA2B2NP01H100D050BA)
Cap Ceramic 10pF 50V NP0 0.5pF Pad SMD 0402 +150°C Automotive T/R; Manufacturer: TDK Corporation; Manufacturer: TDK; AEC Grade: Grade 0; AEC Qualified: Yes; SizeZ_mm: 0.55mm; TempCo: 30ppm/°C
footprint FP-CGA2B2NP01H100D050BA_0402-MFG
footprint FP-CGA2B2NP01H100D050BA_0402-IPC_C
footprint FP-CGA2B2NP01H100D050BA_0402-IPC_B
footprint FP-CGA2B2NP01H100D050BA_0402-IPC_A
pins: 1, 2

## CMP-0034271-1
designator U?, comment TLV709A33DBVR
150-mA 30-V low-dropout (LDO) linear regulator with 3.2-μA supply current 5-SOT-23 -40 to 125; Manufacturer: Texas Instruments; SizeZ_mm: 1.45mm; AEC Qualified: No; Accuracy Percentage: 4%; Dropout Voltage: 1000mV; Max Supply Voltage: 30V; Min Supply Voltage: 4.3V; Nominal Supply Current: 3.2uA; Number Of Outputs: 1; Output Type: Fixed; Output Voltage: 3.3V; Standoff Height: 0mm; TJmax_C: +125°C
footprint DBV0005A-MFG
footprint DBV0005A-IPC_C
footprint DBV0005A-IPC_B
footprint DBV0005A-IPC_A
pins: 1 IN (power), 2 GND (power), 3 NC, 4 NC, 5 OUT (power)

## CMP-0054818-1
designator J?, comment value USB-C Receptacle  (hidden comment: 632 723 300 011)
Connector, Receptacle, USB Type C, R/A; Manufacturer: Wurth Elektronik; CNHeader: FALSE; Current_A: 3A; Gender: Female; Voltage_V: 5V; ContactFinish: Gold; CT: TRUE; Cert_UL: Y
footprint Wurth_632_723_300_011 (Connector, Receptacle, USB Type C, R/A)
pins: A1 GND, A2 SSTXP1, A3 SSTXN1, A4 VBUS, A5 CC1, A6 DP1, A7 DN1, A8 SBU1, A9 VBUS, A10 SSRXN2, A11 SSRXP2, A12 GND, B1 GND, B2 SSTXP2, B3 SSTXN2, B4 VBUS, B5 CC2, B6 DP2, B7 DN2, B8 SBU2, B9 VBUS, B10 SSRXN1, B11 SSRXP1, B12 GND, M1 GND, M2 GND, S1 Shield, S2 Shield, S3 Shield, S4 Shield

## CMP-0064517-1
designator L?, comment ValueDisplayed: 22uH  (hidden comment: 7447462220)
Inductor, Unshielded Drum Core, Ferrite, 22 uH, 1.7 A, 0.102 ohm, TH; Manufacturer: Wurth Elektronik; Isat: 1.7A @ 10% inductance drop; Irms: 1.8A @ 40C rise; Green_Lifecycle: Active; SizeAreaWB_mm2: 64; DCR_ohm: 0.102; Green_REACh: Passed; Value: 22uH; Imax_A: 1.7A; SizeZ_mm: 8.5; SizeX_mm: 6; SizeArea_mm2: 36; Ind_H: 22µH; AEC Category: Q200
footprint WE-TI_5075 (Wurth WE-TI 5075)
pins: 1, 2

## CMP-0066199-1
designator U?, comment ATL431AIDBZR
2.5V Low Iq Adjustable Precision Shunt Regulator, DBZ0003A (SOT-23-3); Alternate Manufacturer: Texas Instruments; SizeAreaWB_mm2: 14.0; U/M: EA; SizeZ_mm: 1.12; SizeX_mm: 2.5; SizeY_mm: 3.0; SizeArea_mm2: 7.5; CompType: IC
footprint DBZ0003A_N (SOT23, 3-Leads, Body 2.9x1.3mm, Pitch 0.95mm, Lead Span 2.4mm, IPC Medium Density)
footprint DBZ0003A_L (SOT23, 3-Leads, Body 2.9x1.3mm, Pitch 0.95mm, Lead Span 2.4mm, IPC High Density)
footprint DBZ0003A_M (SOT23, 3-Leads, Body 2.9x1.3mm, Pitch 0.95mm, Lead Span 2.4mm, IPC Low Density)
pins: 1 CATHODE, 2 REF (in), 3 ANODE

## CMP-0074704-3
designator D?, comment value 40V  (hidden comment: RB521SM-40T2R)
Diode, Schottky, 40 V, 0.2 A, SOD-523; Manufacturer: Rohm; SizeAreaWB_mm2: 5.13; SizeZ_mm: 0.65; AEC Category: Q101; AEC Qualified: N; Vf_V: 540mV; Io_A: 200mA; Value2: 0.54V; SizeArea_mm2: 1.53; TJmax_C: 150°C; Value1: 0.2A; SizeX_mm: 1.7; SizeY_mm: 0.9
footprint SOD-523 (NXP Semiconductor recommended land pattern, nominal STEP model)
pins: 1 K, 2 A

## CMP-0076705-1
designator C?, comment Cap_F: 1µF  VDC_V: 25V  (hidden comment: CGA3E1X7R1E105K080AC)
CAP, CERM, 1 µF, 25 V,+/- 10%, X7R, AEC-Q200 Grade 1, 0603; Manufacturer: TDK; SizeAreaWB_mm2: 4.68; SizeArea_mm2: 1.28; AEC Qualified: Y; AEC Category: Q200; Value: 1uF; TaMax_C: 125°C; SizeZ_mm: 1.0; AEC Grade: 1; Polarized: N; TaMin_C: -55°C; SizeY_mm: 0.8; U/M: EA; CompType: Capacitor; SizeX_mm: 1.6; Cap_Case: 1.6x0.8x0.8mm
footprint 0603S
footprint 0603_HV (Ernesto recommended land pattern.  26 mil between pads.)
footprint 0603L (0603 from SM-752 data)
footprint 0603M (0603 from SM-752 data)
footprint 0603 (0603 from SM-752 data)
pins: 1, 2

## CMP-0077082-2
designator D?, comment MRA4007T3G
Diode, Standard Recovery Rectifier, 1000 V, 1 A, AEC-Q101, SMA; Manufacturer: ON Semiconductor; Value2: 1.1V; TJmax_C: 175°C; SizeX_mm: 5.59; Green_Lifecycle: Active; Value1: 1A; Green_REACh: Passed; AEC Qualified: Y; AEC Category: Q101; SizeArea_mm2: 16.3228; SizeY_mm: 2.92; SizeAreaWB_mm2: 37.3428; Value: 1000V; RJC_CperW: 16.2; SizeZ_mm: 2.87; Vr_V: 1kV
footprint SMA (Molded Diode, 2-Leads, Body 4.3x2.6mm, IPC Medium Density, based on OnSemi component dimensions and land pattern)
pins: 1 K, 2 A

## CMP-0078142-6
designator NT?, comment Net-Tie  (net tie, no BOM)
Single point connection between nets.
footprint Net-Tie_0805_HV_NoOverlay (0805_HV pads tied by 10mil copper trace which can be cut.  An 0805 part can be placed on pads.)
footprint Net-Tie_10milWide_30milLong (10mil net tie, no solder mask opening, no solder paste)
footprint NetTie_0402 (Net Tie 0402 size)
footprint Net-Tie_50milWide_30milLong (50mil net tie, no solder mask opening, no solder paste)
footprint Net-Tie_20milWide_60milLong (20mil net tie, no solder mask opening, no solder paste)
footprint Net-Tie_6mil (10mil net tie, no solder mask opening, no solder paste)
footprint NetTie_1206_NoOverlay (1206 pads tied by 10mil copper trace which can be cut.  Part can be placed on pads.)
footprint Net-Tie_0805_HV (0805_HV pads tied by 10mil copper trace which can be cut.  An 0805 part can be placed on pads.)
footprint NetTie_1206 (1206 pads tied by 10mil copper trace which can be cut.  Part can be placed on pads.)
footprint Net-Tie_5milWide_60milLong (5mil net tie, no solder mask opening, no solder paste)
footprint NetTie_0603 (Net Tie 0603 size)
footprint Net-Tie_4x6mil
footprint Net-Tie_6x8mil
footprint Net-Tie_4milsWide_10milsLong (Net-Tie 4 mils wide by 10 mils long)
footprint Net-Tie6milsWide_20milsLong (6 mils wide by 20 mils long)
footprint Net-Tie7milsWide_20milsLong (7 mils wide by 20 mils long)
footprint Net-Tie_10mil (10mil net tie, no solder mask opening, no solder paste)
pins: 1, 2

## CMP-0083708-1
designator C?, comment VDC_V: 35V  ValueDisplayed: 10µF  (hidden comment: GMK212BBJ106KG-T)
CAP, CERM, 10 µF, 35 V,+/- 10%, X5R, 0805; Manufacturer: Taiyo Yuden; SizeAreaWB_mm2: 6.75; SizeArea_mm2: 2.5; AEC Qualified: N; AEC Category: Q200; Value: 10uF; TaMax_C: 85°C; SizeZ_mm: 1.45; TaMin_C: -55°C; SizeY_mm: 1.25; U/M: EA; CompType: Capacitor; SizeX_mm: 2; Cap_Case: 0805
footprint 0805_HV (0805 with 30mil clearance between pads)
footprint 0805_HV1 (Custom footprint based on analyzing multiple manufacturer recommendations)
footprint 0805 (0805 from SM-752 data)
footprint 0805M (0805 from SM-752 data)
footprint 0805L (0805 from SM-752 data)
pins: 1, 2

## CMP-0085368-1
designator L?, comment ValueDisplayed: 5.6µH  (hidden comment: 74439346056)
Inductor, Shielded, Hyperflux, 5.6 µH, 6.9 A, 0.0165 ohm, SMD; Manufacturer: Wurth Elektronik; Manufacturer: Wurth Electronics; SizeY_mm: 6.45; Value2: 6.9A; Irms: 6.9A @ 40C rise; SizeZ_mm: 6.1; SizeX_mm: 6.65; DCR_ohm: 0.0165; AEC Qualified: N; SizeArea_mm2: 42.8925; AEC Category: Q200; Value: 5.6uH; SizeAreaWB_mm2: 73.0925; Isat: 13.6A @ 30% inductance drop
footprint WE-XHMI_6060 (SMD, 2-Leads, Body 6.65x6.45mm)
pins: 1, 2

## CMP-0086497-1
designator C?, comment VDC_V: 25V  (hidden comment: CGA3E2X8R1E104K080AD)
0.1µF ±10% 25V Ceramic Capacitor X8R 0603 (1608 Metric); Manufacturer: TDK Corporation; SizeZ_mm: 0.95mm; Cap_F: 100nF; TempCo: 15%; AEC Grade: Grade 0; AEC Qualified: Yes; Symbol Name: SYM-CGA3E2X8R1E104K080AD
footprint FP-CGA3E2X8R1E104K080AD_0603-MFG
footprint FP-CGA3E2X8R1E104K080AD_0603-IPC_C
footprint FP-CGA3E2X8R1E104K080AD_0603-IPC_B
footprint FP-CGA3E2X8R1E104K080AD_0603-IPC_A
pins: 1, 2

## CMP-0086802-1
designator U?, comment MP6908GJ-Z
FAST TURN-OFF INTELLIGENT RECTIF; Manufacturer: Monolithic Power Systems; SizeZ_mm: 1mm; Symbol Name: SYM-MP6908GJ-Z
footprint FP-MP6908GJ-Z_TSOT23-6-MFG
footprint FP-MP6908GJ-Z_TSOT23-6-IPC_C
footprint FP-MP6908GJ-Z_TSOT23-6-IPC_B
footprint FP-MP6908GJ-Z_TSOT23-6-IPC_A
pins: 1 HVC (in), 2 VSS (power), 3 SLEW, 4 VDD (power), 5 VG (out), 6 VD (hiz)

## CMP-0092592-1
designator D?, comment STS321050B331
18V Clamp 22A (8/20µs) Ipp Tvs Diode Surface Mount SOD-323; Manufacturer: Eaton; ValueDisplayed: 33pF; Breakdown Voltage: 5.5V; Number Of Channels: 1; SizeZ_mm: 1mm; AEC Qualified: No; Ppk: 400W; VRWM: 5V; TJmax_C: +125°C; Direction: Bidirectional
footprint FP-STS321050B331_SOD-323-MFG
footprint FP-STS321050B331_SOD-323-IPC_C
footprint FP-STS321050B331_SOD-323-IPC_B
footprint FP-STS321050B331_SOD-323-IPC_A
pins: 1, 2

## CMP-0095068-1
designator R?, comment NTCG043JF103FTB
Chip NTC Thermistors (Sensor), Resistance (at 25°C)=10kΩ, Resistance Tolerance (at 25°C)=±1%; Manufacturer: TDK; SizeZ_mm: 0.22mm; B 25 50: 3380K; Value: 10k; B Tolerance: 1%; B 25 100: 3453K; Res_ohm: 10kΩ; B 25 85: 3435K; AEC Qualified: No
footprint FP-NTCG043JF103FTB_SMD2-MFG
footprint FP-NTCG043JF103FTB_SMD2-IPC_C
footprint FP-NTCG043JF103FTB_SMD2-IPC_B
footprint FP-NTCG043JF103FTB_SMD2-IPC_A
pins: 1, 2

## CMP-0097888-1
designator U?, comment TPS54538RQF
3.8-V to 28-V Input, 5-A, 200kHz-2.2MHz, Low IQ Synchronous Buck Converter; Manufacturer: Texas Instruments; TJmax_C: +150°C; Max Supply Voltage: 28V; Switching Frequency: 200-2200kHz; Max Duty Cycle: 98%; Standoff Height: 0mm; Number Of Outputs: 1; Output Voltage: 0.6-27.44V; Nominal Supply Current: 35-250uA; AEC Qualified: No; Min Supply Voltage: 3.8V; Output Type: AdjustableProgrammable; SizeZ_mm: 1mm
footprint RQF0009A-MFG
pins: 1 RT/SYNC, 2 EN (in), 3 FB, 4 GND (power), 5 VIN (power), 6 VIN (power), 7 MODE, 8 SW (power), 9 PG/SS

## CMP-0115938-1
designator C?, comment Cap_F: 470pF  (hidden comment: 885362210009)
WCAP-CSSA Multilayer Ceramic Chip Safety Capacitor, size 1808, X7R Class II, 470pF, 250VAC; Manufacturer: Wurth Elektronik; Manufacturer: Wurth Electronics; Capacitance Tolerance: +/-10%; Case/Size Code: 1808; Dissipation Factor: 2.5%; Impulse Voltage: 2500VDC; Insulation Resistance: 10GOhm; Rated Voltage (AC): 250V; Safety Class: X2; Technical Reference: X7R1808471KB50IFCT10000
footprint WCAP-CSSA_1808_L4.5W2H1.6 (Ceramic Capacitors, body 4.50x2.00mm)
pins: 1, 2

## CMP-0116785-1
designator C?, comment 27u
WCAP-ATG5 Aluminum Electrolytic Capacitor, Radial, THT, D8 x H16mm, 22µF, 400V; Manufacturer: Wurth Elektronik; Manufacturer Part Number: 860021374027; Manufacturer: Wurth Electronics; Capacitance Tolerance: +0%/-40%; Dissipation Factor: 15%; Endurance: 2000h; Leakage Current: 264uA; Ripple Current: 200mA; Technical Reference: ATJE1602203400DSPA7B0LR
footprint WCAP-ATG5_D8H16 (Aluminum Electrolytic Capacitors, 8x16mm)
pins: 1 P, 2 N

## CMP-0120719-1
designator D?, comment Z4DGP406L-HF
Bridge Rectifier Single Phase Standard 600 V Surface Mount Z4-D; Manufacturer: Comchip; AEC Qualified: No; SizeZ_mm: 1.45mm; TJmax_C: 175°C; Vf_V: 600V; Cap_F: 45pF; Forward Current: 4A; Max Surge Forward Current: 150A; Peak Reverse Current: 0.08uA
footprint FP-Z4DGP406L-HF_SMT_8MM1_10MM5-MFG
pins: 1 +, 2 1_~, 3 2_~, 4 -

## CMP-0120965-1
designator J?, comment USB4145-03-0230-C
USB Connectors USB-C Rec 3u Vert 16P SMT 2.3mm TH stakes H7.46mm T+R+Cap; Manufacturer: GCT; Manufacturer: Global Connector Technology; ContactFinish: Gold,Nickel; Current_A: 6.25A; Shrouded: true; Voltage_V: 48V; AEC Qualified: No; Conn Orientation: Vertical; DUT-Pitch_mm: 0.5mm; Is Female: yes; SizeZ_mm: 7.66mm; Standoff Height: 0.05mm; Usb Standard: USB 2.0
footprint FP-USB4145-03-0230-C_CONN_USB-MFG
pins: 1 GND (power), 2 GND (power), 3 GND (power), 4 GND (power), A1 GND (power), A4 VBUS (power), A5 CC1, A6 Dp1 (io), A7 Dn1 (io), A8 SBU1, A9 VBUS (power), A12 GND (power), B1 GND (power), B4 VBUS (power), B5 CC2, B6 Dp2 (io), B7 Dn2 (io), B8 SBU2, B9 VBUS (power), B12 GND (power)

## CMP-0121548-1
designator U?, comment UCG28682
Manufacturer: Texas Instruments; SizeZ_mm: 1mm; Standoff Height: 0mm
footprint REZ0012A-MFG
pins: 1 HV (power), 2 SW (power), 3 PGND (power), 4 FLT, 5 FB, 6 TR, 7 IPK, 8 CDX, 9 FCL, 10 AGND (power), 11 VCC (power), 12 PGND (power)

## CMP-0860569-1
designator C?, comment VDC_V: 25V  ValueDisplayed: 10µF  (hidden comment: GRM188R61E106KA73D)
CAP, CERM, 10 µF, 25 V,+/- 10%, X5R, 0603; Manufacturer: MuRata; SizeZ_mm: 1; AEC Category: Q200; AEC Qualified: N; TaMin_C: -55°C; Cap_Case: 0603; SizeY_mm: 0.8; SizeAreaWB_mm2: 4.68; SizeArea_mm2: 1.28; TaMax_C: 85°C; SizeX_mm: 1.6; Value: 10uF; CompType: Capacitor; U/M: EA
footprint 0603 (0603 from SM-752 data)
footprint 0603M (0603 from SM-752 data)
footprint 0603L (0603 from SM-752 data)
footprint 0603_HV (Ernesto recommended land pattern.  26 mil between pads.)
footprint 0603S
pins: 1, 2

## ECAP_LAYDOWN
designator EC?  value 470uF  Voltage: 25V  (hidden comment: ECAP_LAYDOWN)
25V/470uF D5.5*11mm
footprint CE05.5P254L11
pins: 1 P, 2 N

## Fuse
designator F?, comment 6125FA3A  (value not drawn)
Fuse, 3.15 A, 250VAC/VDC, SMD; Manufacturer: Cooper Bussman; Irating_A: 3A; Interrupt_AC: 50A; Interrupt_DC: 300A; VAC_V: 125V; Rtyp_Ohm: 28m; MeltingTyp: 2.4
footprint 6125FA (Cooper Bussman 6125FA Brick Fuses, recommended land pattern OC-2531 Rev. I 3/07)
footprint FUSE SMT
pins: 1, 2

## MOSFET_N_D56789G4S123
designator Q?, comment CSD17575Q3
MOSFET, N-CH, 30 V, 60 A, DQG0008A (VSON-CLIP-8); Manufacturer: Texas Instruments; Alternate Manufacturer: None; U/M: EA; ChType: N; Value: 30V; Value1: 0.003; Rdson45_ohm: 3.2m; Value2: 23 nC; QgTyp_nC: 23; Vgs_V: 20V; IdsMax_A: 60A; AEC Category: Q101; SizeZ_mm: 1.1; SizeX_mm: 3.3; SizeArea_mm2: 10.89; SizeAreaWB_mm2: 18.49
footprint DQG0008A (SMD, 8-Leads, Body 3.3x3.3mm, Pitch 0.65mm)
footprint DQG0008A_NV (SMD, 8-Leads, Body 3.3x3.3mm, Pitch 0.65mm)
pins: 1 S, 2 S, 3 S, 4 G, 5 D, 6 D, 7 D, 8 D, 9 D

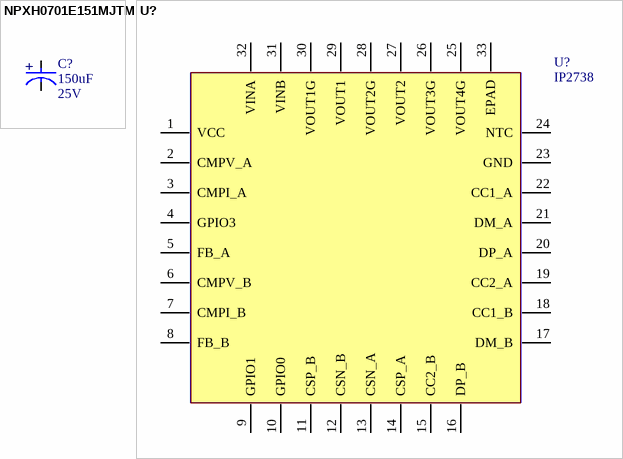
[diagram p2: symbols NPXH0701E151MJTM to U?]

## NPXH0701E151MJTM
designator C?, comment value 150uF  Voltage: 25V  (hidden comment: CAP 25V 150uF D 5.5X7mm)
footprint Ecap_5.5_9_2.5
pins: 1 CATHODE, 2 ANODE

## U?
designator U?, comment IP2738
IP2738 dual port USB PD controller
footprint IP2738
pins: 1 VCC, 2 CMPV_A, 3 CMPI_A, 4 GPIO3, 5 FB_A, 6 CMPV_B, 7 CMPI_B, 8 FB_B, 9 GPIO1, 10 GPIO0, 11 CSP_B, 12 CSN_B, 13 CSN_A, 14 CSP_A, 15 CC2_B, 16 DP_B, 17 DM_B, 18 CC1_B, 19 CC2_A, 20 DP_A, 21 DM_A, 22 CC1_A, 23 GND, 24 NTC, 25 VOUT4G, 26 VOUT3G, 27 VOUT2, 28 VOUT2G, 29 VOUT1, 30 VOUT1G, 31 VINB, 32 VINA, 33 EPAD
